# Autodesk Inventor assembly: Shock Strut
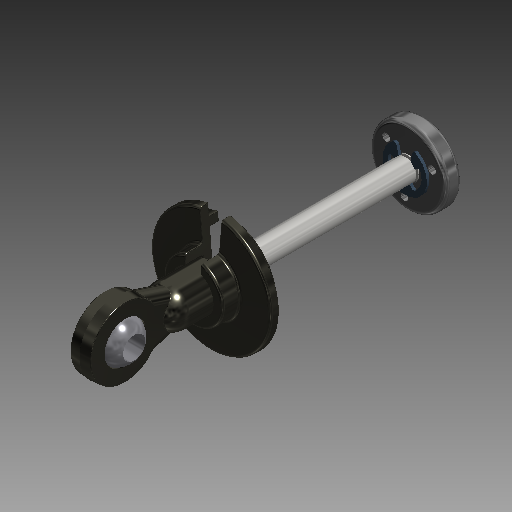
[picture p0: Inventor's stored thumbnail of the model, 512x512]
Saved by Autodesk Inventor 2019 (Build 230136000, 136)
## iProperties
Shininess: 50.0
Compacted: True
Length Units: 11272
Angle Units: 11279
Time Units: 11290
Mass Units: 11286
Length Display Precision: 4
Angle Display Precision: 2
Company: Autodesk
Created: 2000-03
Part Number: Shock Strut
Project: Inventor Samples
Document SubType Name: Assembly
Designer: Autodesk, Inc.
Mass: 3.62337 g
Surface Area: 20.5688 cm^2
Volume: 1.29821 cm^3
Density: 2.79104 g/cm^3
Density: 0.0
Volumn: 0.0
Area: 0.0
PropertySet Name: Model Information
Control State: 0
Master: False
Checked Out: False
Checked Out Date: 2018-05-30
Last Check In Date: 2018-05-30
Title: 1.3 SHOCK
Author: Autodesk, Inc.
Revision Number: A
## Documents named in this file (6)
- C:\Users\itools\Desktop\autodesk_inventor_2018_samples\Models\Assemblies\Suspension\Components\Shock Strut.iam
- C:\Users\itools\Desktop\autodesk_inventor_2018_samples\Models\Assemblies\Suspension\Components\Shock Shaft.ipt
- C:\Users\itools\Desktop\autodesk_inventor_2018_samples\Models\Assemblies\Suspension\Components\E-Clip.ipt
- C:\Users\itools\Desktop\autodesk_inventor_2018_samples\Models\Assemblies\Suspension\Components\Piston.ipt
- C:\Users\itools\Desktop\autodesk_inventor_2018_samples\Models\Assemblies\Suspension\Components\Ball End.iam
- C:\Users\itools\Desktop\autodesk_inventor_2018_samples\Models\Assemblies\Suspension\Components\Spring Cup.ipt
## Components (6 placed, 5 different names)
1. Shock Shaft:1 — Mate:5, Mate:6, Mate:7, Mate:8, Mate:9, Mate:11, Mate:12
2. E-Clip:1 — Mate:5, Mate:6
3. E-Clip:2 — Mate:7, Mate:8, Mate:10
4. Piston:1 — Mate:9, Mate:10
5. Ball End:1 [sub-assembly] — Mate:11, Mate:12, Mate:14, Mate:15
6. Spring Cup:1 — Mate:14, Mate:15
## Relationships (10: Mate 10)
- Mate:5: Shock Shaft:1 ↔ E-Clip:1
- Mate:6: Shock Shaft:1 ↔ E-Clip:1
- Mate:7: Shock Shaft:1 ↔ E-Clip:2
- Mate:8: Shock Shaft:1 ↔ E-Clip:2
- Mate:9: Shock Shaft:1 ↔ Piston:1
- Mate:10: E-Clip:2 ↔ Piston:1
- Mate:11: Shock Shaft:1 ↔ Ball End:1
- Mate:12: Shock Shaft:1 ↔ Ball End:1
- Mate:14: Ball End:1 ↔ Spring Cup:1
- Mate:15: Ball End:1 ↔ Spring Cup:1
